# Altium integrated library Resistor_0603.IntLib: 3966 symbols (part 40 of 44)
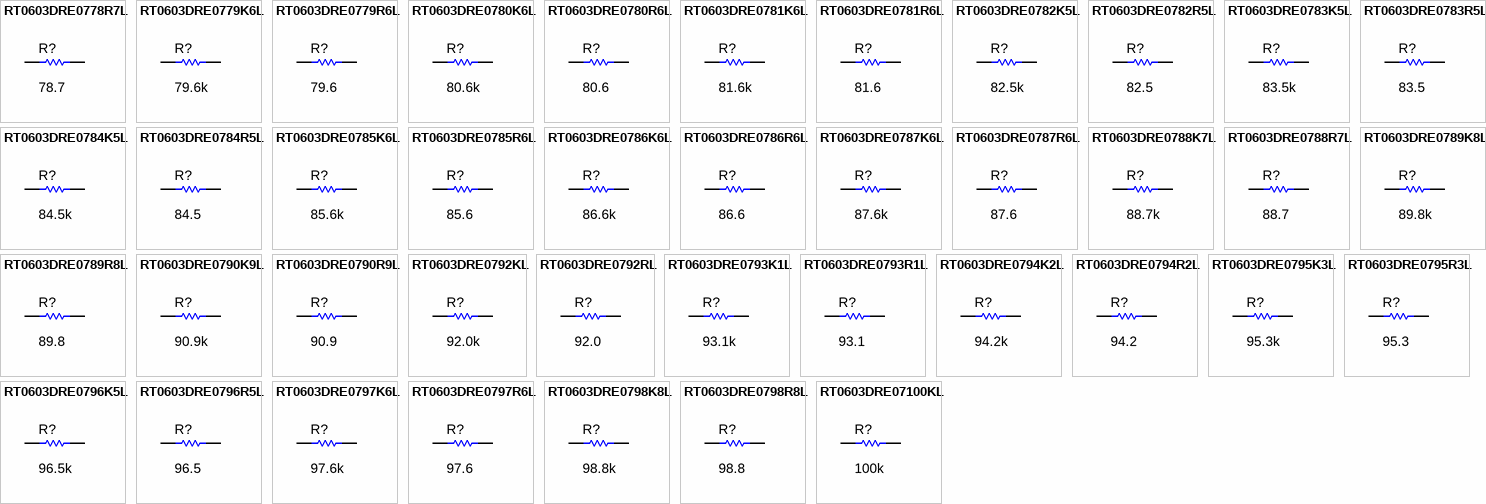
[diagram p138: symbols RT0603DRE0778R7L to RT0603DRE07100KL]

## RT0603DRE0779K6L
designator R?  ValueDisplayed: 79.6k  (hidden comment: RT0603DRE0779K6L)
RES, 79.6 k, 0.5%, 0.1 W, 0603; Manufacturer: Yageo America; CompType: Resistor; Value: 79.6k; Res_ohm: 79600; Value_Code: 79k6; Tolerance_%: 0.5; Power_W: 0.1; Value2: 0.1W; VDC_V: 75; TempCo: 50 ppm/C; SizeArea_mm2: 1.28; SizeX_mm: 1.6; SizeY_mm: 0.8; SizeZ_mm: 1; EIA_Code: E192; U/M: EA; AEC Category: Q200
signal-integrity model Resistor
simulation model Resistor
footprint 0603
footprint 0603M
footprint 0603L
footprint 0603_HV
footprint 0603S
pins: 1, 2

## RT0603DRE0779R6L
designator R?  ValueDisplayed: 79.6  (hidden comment: RT0603DRE0779R6L)
RES, 79.6, 0.5%, 0.1 W, 0603; Manufacturer: Yageo America; CompType: Resistor; Value: 79.6; Value_Code: 79R6; Tolerance_%: 0.5; Power_W: 0.1; Value2: 0.1W; VDC_V: 75; TempCo: 50 ppm/C; SizeArea_mm2: 1.28; SizeX_mm: 1.6; SizeY_mm: 0.8; SizeZ_mm: 1; EIA_Code: E192; U/M: EA; AEC Category: Q200
signal-integrity model Resistor
simulation model Resistor
footprint 0603
footprint 0603M
footprint 0603L
footprint 0603_HV
footprint 0603S
pins: 1, 2

## RT0603DRE0780K6L
designator R?  ValueDisplayed: 80.6k  (hidden comment: RT0603DRE0780K6L)
RES, 80.6 k, 0.5%, 0.1 W, 0603; Manufacturer: Yageo America; CompType: Resistor; Value: 80.6k; Res_ohm: 80600; Value_Code: 80k6; Tolerance_%: 0.5; Power_W: 0.1; Value2: 0.1W; VDC_V: 75; TempCo: 50 ppm/C; SizeArea_mm2: 1.28; SizeX_mm: 1.6; SizeY_mm: 0.8; SizeZ_mm: 1; EIA_Code: E192; U/M: EA; AEC Category: Q200
signal-integrity model Resistor
simulation model Resistor
footprint 0603
footprint 0603M
footprint 0603L
footprint 0603_HV
footprint 0603S
pins: 1, 2

## RT0603DRE0780R6L
designator R?  ValueDisplayed: 80.6  (hidden comment: RT0603DRE0780R6L)
RES, 80.6, 0.5%, 0.1 W, 0603; Manufacturer: Yageo America; CompType: Resistor; Value: 80.6; Value_Code: 80R6; Tolerance_%: 0.5; Power_W: 0.1; Value2: 0.1W; VDC_V: 75; TempCo: 50 ppm/C; SizeArea_mm2: 1.28; SizeX_mm: 1.6; SizeY_mm: 0.8; SizeZ_mm: 1; EIA_Code: E192; U/M: EA; AEC Category: Q200
signal-integrity model Resistor
simulation model Resistor
footprint 0603
footprint 0603M
footprint 0603L
footprint 0603_HV
footprint 0603S
pins: 1, 2

## RT0603DRE0781K6L
designator R?  ValueDisplayed: 81.6k  (hidden comment: RT0603DRE0781K6L)
RES, 81.6 k, 0.5%, 0.1 W, 0603; Manufacturer: Yageo America; CompType: Resistor; Value: 81.6k; Res_ohm: 81600; Value_Code: 81k6; Tolerance_%: 0.5; Power_W: 0.1; Value2: 0.1W; VDC_V: 75; TempCo: 50 ppm/C; SizeArea_mm2: 1.28; SizeX_mm: 1.6; SizeY_mm: 0.8; SizeZ_mm: 1; EIA_Code: E192; U/M: EA; AEC Category: Q200
signal-integrity model Resistor
simulation model Resistor
footprint 0603
footprint 0603M
footprint 0603L
footprint 0603_HV
footprint 0603S
pins: 1, 2

## RT0603DRE0781R6L
designator R?  ValueDisplayed: 81.6  (hidden comment: RT0603DRE0781R6L)
RES, 81.6, 0.5%, 0.1 W, 0603; Manufacturer: Yageo America; CompType: Resistor; Value: 81.6; Value_Code: 81R6; Tolerance_%: 0.5; Power_W: 0.1; Value2: 0.1W; VDC_V: 75; TempCo: 50 ppm/C; SizeArea_mm2: 1.28; SizeX_mm: 1.6; SizeY_mm: 0.8; SizeZ_mm: 1; EIA_Code: E192; U/M: EA; AEC Category: Q200
signal-integrity model Resistor
simulation model Resistor
footprint 0603
footprint 0603M
footprint 0603L
footprint 0603_HV
footprint 0603S
pins: 1, 2

## RT0603DRE0782K5L
designator R?  ValueDisplayed: 82.5k  (hidden comment: RT0603DRE0782K5L)
RES, 82.5 k, 0.5%, 0.1 W, 0603; Manufacturer: Yageo America; CompType: Resistor; Value: 82.5k; Res_ohm: 82500; Value_Code: 82k5; Tolerance_%: 0.5; Power_W: 0.1; Value2: 0.1W; VDC_V: 75; TempCo: 50 ppm/C; SizeArea_mm2: 1.28; SizeX_mm: 1.6; SizeY_mm: 0.8; SizeZ_mm: 1; EIA_Code: E192; U/M: EA; AEC Category: Q200
signal-integrity model Resistor
simulation model Resistor
footprint 0603
footprint 0603M
footprint 0603L
footprint 0603_HV
footprint 0603S
pins: 1, 2

## RT0603DRE0782R5L
designator R?  ValueDisplayed: 82.5  (hidden comment: RT0603DRE0782R5L)
RES, 82.5, 0.5%, 0.1 W, 0603; Manufacturer: Yageo America; CompType: Resistor; Value: 82.5; Value_Code: 82R5; Tolerance_%: 0.5; Power_W: 0.1; Value2: 0.1W; VDC_V: 75; TempCo: 50 ppm/C; SizeArea_mm2: 1.28; SizeX_mm: 1.6; SizeY_mm: 0.8; SizeZ_mm: 1; EIA_Code: E192; U/M: EA; AEC Category: Q200
signal-integrity model Resistor
simulation model Resistor
footprint 0603
footprint 0603M
footprint 0603L
footprint 0603_HV
footprint 0603S
pins: 1, 2

## RT0603DRE0783K5L
designator R?  ValueDisplayed: 83.5k  (hidden comment: RT0603DRE0783K5L)
RES, 83.5 k, 0.5%, 0.1 W, 0603; Manufacturer: Yageo America; CompType: Resistor; Value: 83.5k; Res_ohm: 83500; Value_Code: 83k5; Tolerance_%: 0.5; Power_W: 0.1; Value2: 0.1W; VDC_V: 75; TempCo: 50 ppm/C; SizeArea_mm2: 1.28; SizeX_mm: 1.6; SizeY_mm: 0.8; SizeZ_mm: 1; EIA_Code: E192; U/M: EA; AEC Category: Q200
signal-integrity model Resistor
simulation model Resistor
footprint 0603
footprint 0603M
footprint 0603L
footprint 0603_HV
footprint 0603S
pins: 1, 2

## RT0603DRE0783R5L
designator R?  ValueDisplayed: 83.5  (hidden comment: RT0603DRE0783R5L)
RES, 83.5, 0.5%, 0.1 W, 0603; Manufacturer: Yageo America; CompType: Resistor; Value: 83.5; Value_Code: 83R5; Tolerance_%: 0.5; Power_W: 0.1; Value2: 0.1W; VDC_V: 75; TempCo: 50 ppm/C; SizeArea_mm2: 1.28; SizeX_mm: 1.6; SizeY_mm: 0.8; SizeZ_mm: 1; EIA_Code: E192; U/M: EA; AEC Category: Q200
signal-integrity model Resistor
simulation model Resistor
footprint 0603
footprint 0603M
footprint 0603L
footprint 0603_HV
footprint 0603S
pins: 1, 2

## RT0603DRE0784K5L
designator R?  ValueDisplayed: 84.5k  (hidden comment: RT0603DRE0784K5L)
RES, 84.5 k, 0.5%, 0.1 W, 0603; Manufacturer: Yageo America; CompType: Resistor; Value: 84.5k; Res_ohm: 84500; Value_Code: 84k5; Tolerance_%: 0.5; Power_W: 0.1; Value2: 0.1W; VDC_V: 75; TempCo: 50 ppm/C; SizeArea_mm2: 1.28; SizeX_mm: 1.6; SizeY_mm: 0.8; SizeZ_mm: 1; EIA_Code: E192; U/M: EA; AEC Category: Q200
signal-integrity model Resistor
simulation model Resistor
footprint 0603
footprint 0603M
footprint 0603L
footprint 0603_HV
footprint 0603S
pins: 1, 2

## RT0603DRE0784R5L
designator R?  ValueDisplayed: 84.5  (hidden comment: RT0603DRE0784R5L)
RES, 84.5, 0.5%, 0.1 W, 0603; Manufacturer: Yageo America; CompType: Resistor; Value: 84.5; Value_Code: 84R5; Tolerance_%: 0.5; Power_W: 0.1; Value2: 0.1W; VDC_V: 75; TempCo: 50 ppm/C; SizeArea_mm2: 1.28; SizeX_mm: 1.6; SizeY_mm: 0.8; SizeZ_mm: 1; EIA_Code: E192; U/M: EA; AEC Category: Q200
signal-integrity model Resistor
simulation model Resistor
footprint 0603
footprint 0603M
footprint 0603L
footprint 0603_HV
footprint 0603S
pins: 1, 2

## RT0603DRE0785K6L
designator R?  ValueDisplayed: 85.6k  (hidden comment: RT0603DRE0785K6L)
RES, 85.6 k, 0.5%, 0.1 W, 0603; Manufacturer: Yageo America; CompType: Resistor; Value: 85.6k; Res_ohm: 85600; Value_Code: 85k6; Tolerance_%: 0.5; Power_W: 0.1; Value2: 0.1W; VDC_V: 75; TempCo: 50 ppm/C; SizeArea_mm2: 1.28; SizeX_mm: 1.6; SizeY_mm: 0.8; SizeZ_mm: 1; EIA_Code: E192; U/M: EA; AEC Category: Q200
signal-integrity model Resistor
simulation model Resistor
footprint 0603
footprint 0603M
footprint 0603L
footprint 0603_HV
footprint 0603S
pins: 1, 2

## RT0603DRE0785R6L
designator R?  ValueDisplayed: 85.6  (hidden comment: RT0603DRE0785R6L)
RES, 85.6, 0.5%, 0.1 W, 0603; Manufacturer: Yageo America; CompType: Resistor; Value: 85.6; Value_Code: 85R6; Tolerance_%: 0.5; Power_W: 0.1; Value2: 0.1W; VDC_V: 75; TempCo: 50 ppm/C; SizeArea_mm2: 1.28; SizeX_mm: 1.6; SizeY_mm: 0.8; SizeZ_mm: 1; EIA_Code: E192; U/M: EA; AEC Category: Q200
signal-integrity model Resistor
simulation model Resistor
footprint 0603
footprint 0603M
footprint 0603L
footprint 0603_HV
footprint 0603S
pins: 1, 2

## RT0603DRE0786K6L
designator R?  ValueDisplayed: 86.6k  (hidden comment: RT0603DRE0786K6L)
RES, 86.6 k, 0.5%, 0.1 W, 0603; Manufacturer: Yageo America; CompType: Resistor; Value: 86.6k; Res_ohm: 86600; Value_Code: 86k6; Tolerance_%: 0.5; Power_W: 0.1; Value2: 0.1W; VDC_V: 75; TempCo: 50 ppm/C; SizeArea_mm2: 1.28; SizeX_mm: 1.6; SizeY_mm: 0.8; SizeZ_mm: 1; EIA_Code: E192; U/M: EA; AEC Category: Q200
signal-integrity model Resistor
simulation model Resistor
footprint 0603
footprint 0603M
footprint 0603L
footprint 0603_HV
footprint 0603S
pins: 1, 2

## RT0603DRE0786R6L
designator R?  ValueDisplayed: 86.6  (hidden comment: RT0603DRE0786R6L)
RES, 86.6, 0.5%, 0.1 W, 0603; Manufacturer: Yageo America; CompType: Resistor; Value: 86.6; Value_Code: 86R6; Tolerance_%: 0.5; Power_W: 0.1; Value2: 0.1W; VDC_V: 75; TempCo: 50 ppm/C; SizeArea_mm2: 1.28; SizeX_mm: 1.6; SizeY_mm: 0.8; SizeZ_mm: 1; EIA_Code: E192; U/M: EA; AEC Category: Q200
signal-integrity model Resistor
simulation model Resistor
footprint 0603
footprint 0603M
footprint 0603L
footprint 0603_HV
footprint 0603S
pins: 1, 2

## RT0603DRE0787K6L
designator R?  ValueDisplayed: 87.6k  (hidden comment: RT0603DRE0787K6L)
RES, 87.6 k, 0.5%, 0.1 W, 0603; Manufacturer: Yageo America; CompType: Resistor; Value: 87.6k; Res_ohm: 87600; Value_Code: 87k6; Tolerance_%: 0.5; Power_W: 0.1; Value2: 0.1W; VDC_V: 75; TempCo: 50 ppm/C; SizeArea_mm2: 1.28; SizeX_mm: 1.6; SizeY_mm: 0.8; SizeZ_mm: 1; EIA_Code: E192; U/M: EA; AEC Category: Q200
signal-integrity model Resistor
simulation model Resistor
footprint 0603
footprint 0603M
footprint 0603L
footprint 0603_HV
footprint 0603S
pins: 1, 2

## RT0603DRE0787R6L
designator R?  ValueDisplayed: 87.6  (hidden comment: RT0603DRE0787R6L)
RES, 87.6, 0.5%, 0.1 W, 0603; Manufacturer: Yageo America; CompType: Resistor; Value: 87.6; Value_Code: 87R6; Tolerance_%: 0.5; Power_W: 0.1; Value2: 0.1W; VDC_V: 75; TempCo: 50 ppm/C; SizeArea_mm2: 1.28; SizeX_mm: 1.6; SizeY_mm: 0.8; SizeZ_mm: 1; EIA_Code: E192; U/M: EA; AEC Category: Q200
signal-integrity model Resistor
simulation model Resistor
footprint 0603
footprint 0603M
footprint 0603L
footprint 0603_HV
footprint 0603S
pins: 1, 2

## RT0603DRE0788K7L
designator R?  ValueDisplayed: 88.7k  (hidden comment: RT0603DRE0788K7L)
RES, 88.7 k, 0.5%, 0.1 W, 0603; Manufacturer: Yageo America; CompType: Resistor; Value: 88.7k; Res_ohm: 88700; Value_Code: 88k7; Tolerance_%: 0.5; Power_W: 0.1; Value2: 0.1W; VDC_V: 75; TempCo: 50 ppm/C; SizeArea_mm2: 1.28; SizeX_mm: 1.6; SizeY_mm: 0.8; SizeZ_mm: 1; EIA_Code: E192; U/M: EA; AEC Category: Q200
signal-integrity model Resistor
simulation model Resistor
footprint 0603
footprint 0603M
footprint 0603L
footprint 0603_HV
footprint 0603S
pins: 1, 2

## RT0603DRE0788R7L
designator R?  ValueDisplayed: 88.7  (hidden comment: RT0603DRE0788R7L)
RES, 88.7, 0.5%, 0.1 W, 0603; Manufacturer: Yageo America; CompType: Resistor; Value: 88.7; Value_Code: 88R7; Tolerance_%: 0.5; Power_W: 0.1; Value2: 0.1W; VDC_V: 75; TempCo: 50 ppm/C; SizeArea_mm2: 1.28; SizeX_mm: 1.6; SizeY_mm: 0.8; SizeZ_mm: 1; EIA_Code: E192; U/M: EA; AEC Category: Q200
signal-integrity model Resistor
simulation model Resistor
footprint 0603
footprint 0603M
footprint 0603L
footprint 0603_HV
footprint 0603S
pins: 1, 2

## RT0603DRE0789K8L
designator R?  ValueDisplayed: 89.8k  (hidden comment: RT0603DRE0789K8L)
RES, 89.8 k, 0.5%, 0.1 W, 0603; Manufacturer: Yageo America; CompType: Resistor; Value: 89.8k; Res_ohm: 89800; Value_Code: 89k8; Tolerance_%: 0.5; Power_W: 0.1; Value2: 0.1W; VDC_V: 75; TempCo: 50 ppm/C; SizeArea_mm2: 1.28; SizeX_mm: 1.6; SizeY_mm: 0.8; SizeZ_mm: 1; EIA_Code: E192; U/M: EA; AEC Category: Q200
signal-integrity model Resistor
simulation model Resistor
footprint 0603
footprint 0603M
footprint 0603L
footprint 0603_HV
footprint 0603S
pins: 1, 2

## RT0603DRE0789R8L
designator R?  ValueDisplayed: 89.8  (hidden comment: RT0603DRE0789R8L)
RES, 89.8, 0.5%, 0.1 W, 0603; Manufacturer: Yageo America; CompType: Resistor; Value: 89.8; Value_Code: 89R8; Tolerance_%: 0.5; Power_W: 0.1; Value2: 0.1W; VDC_V: 75; TempCo: 50 ppm/C; SizeArea_mm2: 1.28; SizeX_mm: 1.6; SizeY_mm: 0.8; SizeZ_mm: 1; EIA_Code: E192; U/M: EA; AEC Category: Q200
signal-integrity model Resistor
simulation model Resistor
footprint 0603
footprint 0603M
footprint 0603L
footprint 0603_HV
footprint 0603S
pins: 1, 2

## RT0603DRE0790K9L
designator R?  ValueDisplayed: 90.9k  (hidden comment: RT0603DRE0790K9L)
RES, 90.9 k, 0.5%, 0.1 W, 0603; Manufacturer: Yageo America; CompType: Resistor; Value: 90.9k; Res_ohm: 90900; Value_Code: 90k9; Tolerance_%: 0.5; Power_W: 0.1; Value2: 0.1W; VDC_V: 75; TempCo: 50 ppm/C; SizeArea_mm2: 1.28; SizeX_mm: 1.6; SizeY_mm: 0.8; SizeZ_mm: 1; EIA_Code: E192; U/M: EA; AEC Category: Q200
signal-integrity model Resistor
simulation model Resistor
footprint 0603
footprint 0603M
footprint 0603L
footprint 0603_HV
footprint 0603S
pins: 1, 2

## RT0603DRE0790R9L
designator R?  ValueDisplayed: 90.9  (hidden comment: RT0603DRE0790R9L)
RES, 90.9, 0.5%, 0.1 W, 0603; Manufacturer: Yageo America; CompType: Resistor; Value: 90.9; Value_Code: 90R9; Tolerance_%: 0.5; Power_W: 0.1; Value2: 0.1W; VDC_V: 75; TempCo: 50 ppm/C; SizeArea_mm2: 1.28; SizeX_mm: 1.6; SizeY_mm: 0.8; SizeZ_mm: 1; EIA_Code: E192; U/M: EA; AEC Category: Q200
signal-integrity model Resistor
simulation model Resistor
footprint 0603
footprint 0603M
footprint 0603L
footprint 0603_HV
footprint 0603S
pins: 1, 2

## RT0603DRE0792KL
designator R?  ValueDisplayed: 92.0k  (hidden comment: RT0603DRE0792KL)
RES, 92.0 k, 0.5%, 0.1 W, 0603; Manufacturer: Yageo America; CompType: Resistor; Value: 92.0k; Res_ohm: 92000; Value_Code: 92k0; Tolerance_%: 0.5; Power_W: 0.1; Value2: 0.1W; VDC_V: 75; TempCo: 50 ppm/C; SizeArea_mm2: 1.28; SizeX_mm: 1.6; SizeY_mm: 0.8; SizeZ_mm: 1; EIA_Code: E192; U/M: EA; AEC Category: Q200
signal-integrity model Resistor
simulation model Resistor
footprint 0603
footprint 0603M
footprint 0603L
footprint 0603_HV
footprint 0603S
pins: 1, 2

## RT0603DRE0792RL
designator R?  ValueDisplayed: 92.0  (hidden comment: RT0603DRE0792RL)
RES, 92.0, 0.5%, 0.1 W, 0603; Manufacturer: Yageo America; CompType: Resistor; Value: 92.0; Res_ohm: 92; Value_Code: 92R0; Tolerance_%: 0.5; Power_W: 0.1; Value2: 0.1W; VDC_V: 75; TempCo: 50 ppm/C; SizeArea_mm2: 1.28; SizeX_mm: 1.6; SizeY_mm: 0.8; SizeZ_mm: 1; EIA_Code: E192; U/M: EA; AEC Category: Q200
signal-integrity model Resistor
simulation model Resistor
footprint 0603
footprint 0603M
footprint 0603L
footprint 0603_HV
footprint 0603S
pins: 1, 2

## RT0603DRE0793K1L
designator R?  ValueDisplayed: 93.1k  (hidden comment: RT0603DRE0793K1L)
RES, 93.1 k, 0.5%, 0.1 W, 0603; Manufacturer: Yageo America; CompType: Resistor; Value: 93.1k; Res_ohm: 93100; Value_Code: 93k1; Tolerance_%: 0.5; Power_W: 0.1; Value2: 0.1W; VDC_V: 75; TempCo: 50 ppm/C; SizeArea_mm2: 1.28; SizeX_mm: 1.6; SizeY_mm: 0.8; SizeZ_mm: 1; EIA_Code: E192; U/M: EA; AEC Category: Q200
signal-integrity model Resistor
simulation model Resistor
footprint 0603
footprint 0603M
footprint 0603L
footprint 0603_HV
footprint 0603S
pins: 1, 2

## RT0603DRE0793R1L
designator R?  ValueDisplayed: 93.1  (hidden comment: RT0603DRE0793R1L)
RES, 93.1, 0.5%, 0.1 W, 0603; Manufacturer: Yageo America; CompType: Resistor; Value: 93.1; Value_Code: 93R1; Tolerance_%: 0.5; Power_W: 0.1; Value2: 0.1W; VDC_V: 75; TempCo: 50 ppm/C; SizeArea_mm2: 1.28; SizeX_mm: 1.6; SizeY_mm: 0.8; SizeZ_mm: 1; EIA_Code: E192; U/M: EA; AEC Category: Q200
signal-integrity model Resistor
simulation model Resistor
footprint 0603
footprint 0603M
footprint 0603L
footprint 0603_HV
footprint 0603S
pins: 1, 2

## RT0603DRE0794K2L
designator R?  ValueDisplayed: 94.2k  (hidden comment: RT0603DRE0794K2L)
RES, 94.2 k, 0.5%, 0.1 W, 0603; Manufacturer: Yageo America; CompType: Resistor; Value: 94.2k; Res_ohm: 94200; Value_Code: 94k2; Tolerance_%: 0.5; Power_W: 0.1; Value2: 0.1W; VDC_V: 75; TempCo: 50 ppm/C; SizeArea_mm2: 1.28; SizeX_mm: 1.6; SizeY_mm: 0.8; SizeZ_mm: 1; EIA_Code: E192; U/M: EA; AEC Category: Q200
signal-integrity model Resistor
simulation model Resistor
footprint 0603
footprint 0603M
footprint 0603L
footprint 0603_HV
footprint 0603S
pins: 1, 2

## RT0603DRE0794R2L
designator R?  ValueDisplayed: 94.2  (hidden comment: RT0603DRE0794R2L)
RES, 94.2, 0.5%, 0.1 W, 0603; Manufacturer: Yageo America; CompType: Resistor; Value: 94.2; Value_Code: 94R2; Tolerance_%: 0.5; Power_W: 0.1; Value2: 0.1W; VDC_V: 75; TempCo: 50 ppm/C; SizeArea_mm2: 1.28; SizeX_mm: 1.6; SizeY_mm: 0.8; SizeZ_mm: 1; EIA_Code: E192; U/M: EA; AEC Category: Q200
signal-integrity model Resistor
simulation model Resistor
footprint 0603
footprint 0603M
footprint 0603L
footprint 0603_HV
footprint 0603S
pins: 1, 2

## RT0603DRE0795K3L
designator R?  ValueDisplayed: 95.3k  (hidden comment: RT0603DRE0795K3L)
RES, 95.3 k, 0.5%, 0.1 W, 0603; Manufacturer: Yageo America; CompType: Resistor; Value: 95.3k; Res_ohm: 95300; Value_Code: 95k3; Tolerance_%: 0.5; Power_W: 0.1; Value2: 0.1W; VDC_V: 75; TempCo: 50 ppm/C; SizeArea_mm2: 1.28; SizeX_mm: 1.6; SizeY_mm: 0.8; SizeZ_mm: 1; EIA_Code: E192; U/M: EA; AEC Category: Q200
signal-integrity model Resistor
simulation model Resistor
footprint 0603
footprint 0603M
footprint 0603L
footprint 0603_HV
footprint 0603S
pins: 1, 2

## RT0603DRE0795R3L
designator R?  ValueDisplayed: 95.3  (hidden comment: RT0603DRE0795R3L)
RES, 95.3, 0.5%, 0.1 W, 0603; Manufacturer: Yageo America; CompType: Resistor; Value: 95.3; Value_Code: 95R3; Tolerance_%: 0.5; Power_W: 0.1; Value2: 0.1W; VDC_V: 75; TempCo: 50 ppm/C; SizeArea_mm2: 1.28; SizeX_mm: 1.6; SizeY_mm: 0.8; SizeZ_mm: 1; EIA_Code: E192; U/M: EA; AEC Category: Q200
signal-integrity model Resistor
simulation model Resistor
footprint 0603
footprint 0603M
footprint 0603L
footprint 0603_HV
footprint 0603S
pins: 1, 2

## RT0603DRE0796K5L
designator R?  ValueDisplayed: 96.5k  (hidden comment: RT0603DRE0796K5L)
RES, 96.5 k, 0.5%, 0.1 W, 0603; Manufacturer: Yageo America; CompType: Resistor; Value: 96.5k; Res_ohm: 96500; Value_Code: 96k5; Tolerance_%: 0.5; Power_W: 0.1; Value2: 0.1W; VDC_V: 75; TempCo: 50 ppm/C; SizeArea_mm2: 1.28; SizeX_mm: 1.6; SizeY_mm: 0.8; SizeZ_mm: 1; EIA_Code: E192; U/M: EA; AEC Category: Q200
signal-integrity model Resistor
simulation model Resistor
footprint 0603
footprint 0603M
footprint 0603L
footprint 0603_HV
footprint 0603S
pins: 1, 2

## RT0603DRE0796R5L
designator R?  ValueDisplayed: 96.5  (hidden comment: RT0603DRE0796R5L)
RES, 96.5, 0.5%, 0.1 W, 0603; Manufacturer: Yageo America; CompType: Resistor; Value: 96.5; Value_Code: 96R5; Tolerance_%: 0.5; Power_W: 0.1; Value2: 0.1W; VDC_V: 75; TempCo: 50 ppm/C; SizeArea_mm2: 1.28; SizeX_mm: 1.6; SizeY_mm: 0.8; SizeZ_mm: 1; EIA_Code: E192; U/M: EA; AEC Category: Q200
signal-integrity model Resistor
simulation model Resistor
footprint 0603
footprint 0603M
footprint 0603L
footprint 0603_HV
footprint 0603S
pins: 1, 2

## RT0603DRE0797K6L
designator R?  ValueDisplayed: 97.6k  (hidden comment: RT0603DRE0797K6L)
RES, 97.6 k, 0.5%, 0.1 W, 0603; Manufacturer: Yageo America; CompType: Resistor; Value: 97.6k; Res_ohm: 97600; Value_Code: 97k6; Tolerance_%: 0.5; Power_W: 0.1; Value2: 0.1W; VDC_V: 75; TempCo: 50 ppm/C; SizeArea_mm2: 1.28; SizeX_mm: 1.6; SizeY_mm: 0.8; SizeZ_mm: 1; EIA_Code: E192; U/M: EA; AEC Category: Q200
signal-integrity model Resistor
simulation model Resistor
footprint 0603
footprint 0603M
footprint 0603L
footprint 0603_HV
footprint 0603S
pins: 1, 2

## RT0603DRE0797R6L
designator R?  ValueDisplayed: 97.6  (hidden comment: RT0603DRE0797R6L)
RES, 97.6, 0.5%, 0.1 W, 0603; Manufacturer: Yageo America; CompType: Resistor; Value: 97.6; Value_Code: 97R6; Tolerance_%: 0.5; Power_W: 0.1; Value2: 0.1W; VDC_V: 75; TempCo: 50 ppm/C; SizeArea_mm2: 1.28; SizeX_mm: 1.6; SizeY_mm: 0.8; SizeZ_mm: 1; EIA_Code: E192; U/M: EA; AEC Category: Q200
signal-integrity model Resistor
simulation model Resistor
footprint 0603
footprint 0603M
footprint 0603L
footprint 0603_HV
footprint 0603S
pins: 1, 2

## RT0603DRE0798K8L
designator R?  ValueDisplayed: 98.8k  (hidden comment: RT0603DRE0798K8L)
RES, 98.8 k, 0.5%, 0.1 W, 0603; Manufacturer: Yageo America; CompType: Resistor; Value: 98.8k; Res_ohm: 98800; Value_Code: 98k8; Tolerance_%: 0.5; Power_W: 0.1; Value2: 0.1W; VDC_V: 75; TempCo: 50 ppm/C; SizeArea_mm2: 1.28; SizeX_mm: 1.6; SizeY_mm: 0.8; SizeZ_mm: 1; EIA_Code: E192; U/M: EA; AEC Category: Q200
signal-integrity model Resistor
simulation model Resistor
footprint 0603
footprint 0603M
footprint 0603L
footprint 0603_HV
footprint 0603S
pins: 1, 2

## RT0603DRE0798R8L
designator R?  ValueDisplayed: 98.8  (hidden comment: RT0603DRE0798R8L)
RES, 98.8, 0.5%, 0.1 W, 0603; Manufacturer: Yageo America; CompType: Resistor; Value: 98.8; Value_Code: 98R8; Tolerance_%: 0.5; Power_W: 0.1; Value2: 0.1W; VDC_V: 75; TempCo: 50 ppm/C; SizeArea_mm2: 1.28; SizeX_mm: 1.6; SizeY_mm: 0.8; SizeZ_mm: 1; EIA_Code: E192; U/M: EA; AEC Category: Q200
signal-integrity model Resistor
simulation model Resistor
footprint 0603
footprint 0603M
footprint 0603L
footprint 0603_HV
footprint 0603S
pins: 1, 2

## RT0603DRE07100KL
designator R?  ValueDisplayed: 100k  (hidden comment: RT0603DRE07100KL)
RES, 100 k, 0.5%, 0.1 W, 0603; Manufacturer: Yageo America; CompType: Resistor; Value: 100k; Res_ohm: 100000; Tolerance_%: 0.5; Power_W: 0.1; Value2: 0.1W; VDC_V: 75; TempCo: 50 ppm/C; SizeArea_mm2: 1.28; SizeX_mm: 1.6; SizeY_mm: 0.8; SizeZ_mm: 1; EIA_Code: E192; U/M: EA; AEC Category: Q200
signal-integrity model Resistor
simulation model Resistor
footprint 0603
footprint 0603M
footprint 0603L
footprint 0603_HV
footprint 0603S
pins: 1, 2

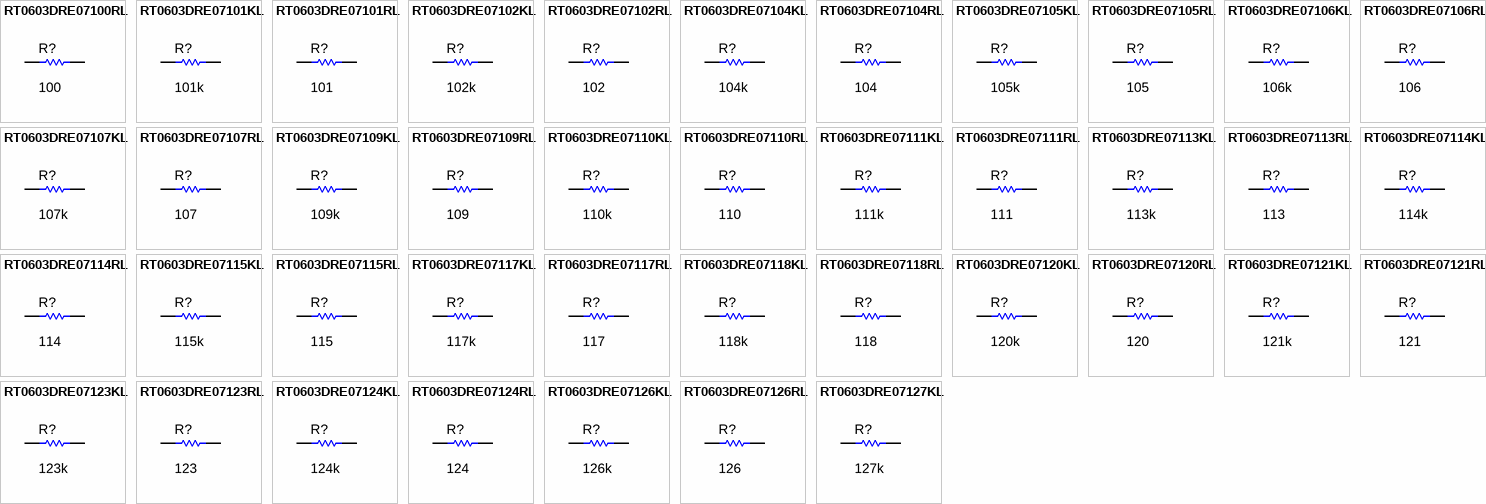
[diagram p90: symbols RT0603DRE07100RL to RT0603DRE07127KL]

## RT0603DRE07100RL
designator R?  ValueDisplayed: 100  (hidden comment: RT0603DRE07100RL)
RES, 100, 0.5%, 0.1 W, 0603; Manufacturer: Yageo America; CompType: Resistor; Value: 100; Value_Code: 100R; Tolerance_%: 0.5; Power_W: 0.1; Value2: 0.1W; VDC_V: 75; TempCo: 50 ppm/C; SizeArea_mm2: 1.28; SizeX_mm: 1.6; SizeY_mm: 0.8; SizeZ_mm: 1; EIA_Code: E192; U/M: EA; AEC Category: Q200
signal-integrity model Resistor
simulation model Resistor
footprint 0603
footprint 0603M
footprint 0603L
footprint 0603_HV
footprint 0603S
pins: 1, 2

## RT0603DRE07101KL
designator R?  ValueDisplayed: 101k  (hidden comment: RT0603DRE07101KL)
RES, 101 k, 0.5%, 0.1 W, 0603; Manufacturer: Yageo America; CompType: Resistor; Value: 101k; Res_ohm: 101000; Tolerance_%: 0.5; Power_W: 0.1; Value2: 0.1W; VDC_V: 75; TempCo: 50 ppm/C; SizeArea_mm2: 1.28; SizeX_mm: 1.6; SizeY_mm: 0.8; SizeZ_mm: 1; EIA_Code: E192; U/M: EA; AEC Category: Q200
signal-integrity model Resistor
simulation model Resistor
footprint 0603
footprint 0603M
footprint 0603L
footprint 0603_HV
footprint 0603S
pins: 1, 2

## RT0603DRE07101RL
designator R?  ValueDisplayed: 101  (hidden comment: RT0603DRE07101RL)
RES, 101, 0.5%, 0.1 W, 0603; Manufacturer: Yageo America; CompType: Resistor; Value: 101; Value_Code: 101R; Tolerance_%: 0.5; Power_W: 0.1; Value2: 0.1W; VDC_V: 75; TempCo: 50 ppm/C; SizeArea_mm2: 1.28; SizeX_mm: 1.6; SizeY_mm: 0.8; SizeZ_mm: 1; EIA_Code: E192; U/M: EA; AEC Category: Q200
signal-integrity model Resistor
simulation model Resistor
footprint 0603
footprint 0603M
footprint 0603L
footprint 0603_HV
footprint 0603S
pins: 1, 2

## RT0603DRE07102KL
designator R?  ValueDisplayed: 102k  (hidden comment: RT0603DRE07102KL)
RES, 102 k, 0.5%, 0.1 W, 0603; Manufacturer: Yageo America; CompType: Resistor; Value: 102k; Res_ohm: 102000; Tolerance_%: 0.5; Power_W: 0.1; Value2: 0.1W; VDC_V: 75; TempCo: 50 ppm/C; SizeArea_mm2: 1.28; SizeX_mm: 1.6; SizeY_mm: 0.8; SizeZ_mm: 1; EIA_Code: E192; U/M: EA; AEC Category: Q200
signal-integrity model Resistor
simulation model Resistor
footprint 0603
footprint 0603M
footprint 0603L
footprint 0603_HV
footprint 0603S
pins: 1, 2

## RT0603DRE07102RL
designator R?  ValueDisplayed: 102  (hidden comment: RT0603DRE07102RL)
RES, 102, 0.5%, 0.1 W, 0603; Manufacturer: Yageo America; CompType: Resistor; Value: 102; Value_Code: 102R; Tolerance_%: 0.5; Power_W: 0.1; Value2: 0.1W; VDC_V: 75; TempCo: 50 ppm/C; SizeArea_mm2: 1.28; SizeX_mm: 1.6; SizeY_mm: 0.8; SizeZ_mm: 1; EIA_Code: E192; U/M: EA; AEC Category: Q200
signal-integrity model Resistor
simulation model Resistor
footprint 0603
footprint 0603M
footprint 0603L
footprint 0603_HV
footprint 0603S
pins: 1, 2

## RT0603DRE07104KL
designator R?  ValueDisplayed: 104k  (hidden comment: RT0603DRE07104KL)
RES, 104 k, 0.5%, 0.1 W, 0603; Manufacturer: Yageo America; CompType: Resistor; Value: 104k; Res_ohm: 104000; Tolerance_%: 0.5; Power_W: 0.1; Value2: 0.1W; VDC_V: 75; TempCo: 50 ppm/C; SizeArea_mm2: 1.28; SizeX_mm: 1.6; SizeY_mm: 0.8; SizeZ_mm: 1; EIA_Code: E192; U/M: EA; AEC Category: Q200
signal-integrity model Resistor
simulation model Resistor
footprint 0603
footprint 0603M
footprint 0603L
footprint 0603_HV
footprint 0603S
pins: 1, 2

## RT0603DRE07104RL
designator R?  ValueDisplayed: 104  (hidden comment: RT0603DRE07104RL)
RES, 104, 0.5%, 0.1 W, 0603; Manufacturer: Yageo America; CompType: Resistor; Value: 104; Value_Code: 104R; Tolerance_%: 0.5; Power_W: 0.1; Value2: 0.1W; VDC_V: 75; TempCo: 50 ppm/C; SizeArea_mm2: 1.28; SizeX_mm: 1.6; SizeY_mm: 0.8; SizeZ_mm: 1; EIA_Code: E192; U/M: EA; AEC Category: Q200
signal-integrity model Resistor
simulation model Resistor
footprint 0603
footprint 0603M
footprint 0603L
footprint 0603_HV
footprint 0603S
pins: 1, 2

## RT0603DRE07105KL
designator R?  ValueDisplayed: 105k  (hidden comment: RT0603DRE07105KL)
RES, 105 k, 0.5%, 0.1 W, 0603; Manufacturer: Yageo America; CompType: Resistor; Value: 105k; Res_ohm: 105000; Tolerance_%: 0.5; Power_W: 0.1; Value2: 0.1W; VDC_V: 75; TempCo: 50 ppm/C; SizeArea_mm2: 1.28; SizeX_mm: 1.6; SizeY_mm: 0.8; SizeZ_mm: 1; EIA_Code: E192; U/M: EA; AEC Category: Q200
signal-integrity model Resistor
simulation model Resistor
footprint 0603
footprint 0603M
footprint 0603L
footprint 0603_HV
footprint 0603S
pins: 1, 2

## RT0603DRE07105RL
designator R?  ValueDisplayed: 105  (hidden comment: RT0603DRE07105RL)
RES, 105, 0.5%, 0.1 W, 0603; Manufacturer: Yageo America; CompType: Resistor; Value: 105; Value_Code: 105R; Tolerance_%: 0.5; Power_W: 0.1; Value2: 0.1W; VDC_V: 75; TempCo: 50 ppm/C; SizeArea_mm2: 1.28; SizeX_mm: 1.6; SizeY_mm: 0.8; SizeZ_mm: 1; EIA_Code: E192; U/M: EA; AEC Category: Q200
signal-integrity model Resistor
simulation model Resistor
footprint 0603
footprint 0603M
footprint 0603L
footprint 0603_HV
footprint 0603S
pins: 1, 2

## RT0603DRE07106KL
designator R?  ValueDisplayed: 106k  (hidden comment: RT0603DRE07106KL)
RES, 106 k, 0.5%, 0.1 W, 0603; Manufacturer: Yageo America; CompType: Resistor; Value: 106k; Res_ohm: 106000; Tolerance_%: 0.5; Power_W: 0.1; Value2: 0.1W; VDC_V: 75; TempCo: 50 ppm/C; SizeArea_mm2: 1.28; SizeX_mm: 1.6; SizeY_mm: 0.8; SizeZ_mm: 1; EIA_Code: E192; U/M: EA; AEC Category: Q200
signal-integrity model Resistor
simulation model Resistor
footprint 0603
footprint 0603M
footprint 0603L
footprint 0603_HV
footprint 0603S
pins: 1, 2

## RT0603DRE07106RL
designator R?  ValueDisplayed: 106  (hidden comment: RT0603DRE07106RL)
RES, 106, 0.5%, 0.1 W, 0603; Manufacturer: Yageo America; CompType: Resistor; Value: 106; Value_Code: 106R; Tolerance_%: 0.5; Power_W: 0.1; Value2: 0.1W; VDC_V: 75; TempCo: 50 ppm/C; SizeArea_mm2: 1.28; SizeX_mm: 1.6; SizeY_mm: 0.8; SizeZ_mm: 1; EIA_Code: E192; U/M: EA; AEC Category: Q200
signal-integrity model Resistor
simulation model Resistor
footprint 0603
footprint 0603M
footprint 0603L
footprint 0603_HV
footprint 0603S
pins: 1, 2

## RT0603DRE07107KL
designator R?  ValueDisplayed: 107k  (hidden comment: RT0603DRE07107KL)
RES, 107 k, 0.5%, 0.1 W, 0603; Manufacturer: Yageo America; CompType: Resistor; Value: 107k; Res_ohm: 107000; Tolerance_%: 0.5; Power_W: 0.1; Value2: 0.1W; VDC_V: 75; TempCo: 50 ppm/C; SizeArea_mm2: 1.28; SizeX_mm: 1.6; SizeY_mm: 0.8; SizeZ_mm: 1; EIA_Code: E192; U/M: EA; AEC Category: Q200
signal-integrity model Resistor
simulation model Resistor
footprint 0603
footprint 0603M
footprint 0603L
footprint 0603_HV
footprint 0603S
pins: 1, 2

## RT0603DRE07107RL
designator R?  ValueDisplayed: 107  (hidden comment: RT0603DRE07107RL)
RES, 107, 0.5%, 0.1 W, 0603; Manufacturer: Yageo America; CompType: Resistor; Value: 107; Value_Code: 107R; Tolerance_%: 0.5; Power_W: 0.1; Value2: 0.1W; VDC_V: 75; TempCo: 50 ppm/C; SizeArea_mm2: 1.28; SizeX_mm: 1.6; SizeY_mm: 0.8; SizeZ_mm: 1; EIA_Code: E192; U/M: EA; AEC Category: Q200
signal-integrity model Resistor
simulation model Resistor
footprint 0603
footprint 0603M
footprint 0603L
footprint 0603_HV
footprint 0603S
pins: 1, 2

## RT0603DRE07109KL
designator R?  ValueDisplayed: 109k  (hidden comment: RT0603DRE07109KL)
RES, 109 k, 0.5%, 0.1 W, 0603; Manufacturer: Yageo America; CompType: Resistor; Value: 109k; Res_ohm: 109000; Tolerance_%: 0.5; Power_W: 0.1; Value2: 0.1W; VDC_V: 75; TempCo: 50 ppm/C; SizeArea_mm2: 1.28; SizeX_mm: 1.6; SizeY_mm: 0.8; SizeZ_mm: 1; EIA_Code: E192; U/M: EA; AEC Category: Q200
signal-integrity model Resistor
simulation model Resistor
footprint 0603
footprint 0603M
footprint 0603L
footprint 0603_HV
footprint 0603S
pins: 1, 2

## RT0603DRE07109RL
designator R?  ValueDisplayed: 109  (hidden comment: RT0603DRE07109RL)
RES, 109, 0.5%, 0.1 W, 0603; Manufacturer: Yageo America; CompType: Resistor; Value: 109; Value_Code: 109R; Tolerance_%: 0.5; Power_W: 0.1; Value2: 0.1W; VDC_V: 75; TempCo: 50 ppm/C; SizeArea_mm2: 1.28; SizeX_mm: 1.6; SizeY_mm: 0.8; SizeZ_mm: 1; EIA_Code: E192; U/M: EA; AEC Category: Q200
signal-integrity model Resistor
simulation model Resistor
footprint 0603
footprint 0603M
footprint 0603L
footprint 0603_HV
footprint 0603S
pins: 1, 2

## RT0603DRE07110KL
designator R?  ValueDisplayed: 110k  (hidden comment: RT0603DRE07110KL)
RES, 110 k, 0.5%, 0.1 W, 0603; Manufacturer: Yageo America; CompType: Resistor; Value: 110k; Res_ohm: 110000; Tolerance_%: 0.5; Power_W: 0.1; Value2: 0.1W; VDC_V: 75; TempCo: 50 ppm/C; SizeArea_mm2: 1.28; SizeX_mm: 1.6; SizeY_mm: 0.8; SizeZ_mm: 1; EIA_Code: E192; U/M: EA; AEC Category: Q200
signal-integrity model Resistor
simulation model Resistor
footprint 0603
footprint 0603M
footprint 0603L
footprint 0603_HV
footprint 0603S
pins: 1, 2

## RT0603DRE07110RL
designator R?  ValueDisplayed: 110  (hidden comment: RT0603DRE07110RL)
RES, 110, 0.5%, 0.1 W, 0603; Manufacturer: Yageo America; CompType: Resistor; Value: 110; Value_Code: 110R; Tolerance_%: 0.5; Power_W: 0.1; Value2: 0.1W; VDC_V: 75; TempCo: 50 ppm/C; SizeArea_mm2: 1.28; SizeX_mm: 1.6; SizeY_mm: 0.8; SizeZ_mm: 1; EIA_Code: E192; U/M: EA; AEC Category: Q200
signal-integrity model Resistor
simulation model Resistor
footprint 0603
footprint 0603M
footprint 0603L
footprint 0603_HV
footprint 0603S
pins: 1, 2

## RT0603DRE07111KL
designator R?  ValueDisplayed: 111k  (hidden comment: RT0603DRE07111KL)
RES, 111 k, 0.5%, 0.1 W, 0603; Manufacturer: Yageo America; CompType: Resistor; Value: 111k; Res_ohm: 111000; Tolerance_%: 0.5; Power_W: 0.1; Value2: 0.1W; VDC_V: 75; TempCo: 50 ppm/C; SizeArea_mm2: 1.28; SizeX_mm: 1.6; SizeY_mm: 0.8; SizeZ_mm: 1; EIA_Code: E192; U/M: EA; AEC Category: Q200
signal-integrity model Resistor
simulation model Resistor
footprint 0603
footprint 0603M
footprint 0603L
footprint 0603_HV
footprint 0603S
pins: 1, 2

## RT0603DRE07111RL
designator R?  ValueDisplayed: 111  (hidden comment: RT0603DRE07111RL)
RES, 111, 0.5%, 0.1 W, 0603; Manufacturer: Yageo America; CompType: Resistor; Value: 111; Value_Code: 111R; Tolerance_%: 0.5; Power_W: 0.1; Value2: 0.1W; VDC_V: 75; TempCo: 50 ppm/C; SizeArea_mm2: 1.28; SizeX_mm: 1.6; SizeY_mm: 0.8; SizeZ_mm: 1; EIA_Code: E192; U/M: EA; AEC Category: Q200
signal-integrity model Resistor
simulation model Resistor
footprint 0603
footprint 0603M
footprint 0603L
footprint 0603_HV
footprint 0603S
pins: 1, 2

## RT0603DRE07113KL
designator R?  ValueDisplayed: 113k  (hidden comment: RT0603DRE07113KL)
RES, 113 k, 0.5%, 0.1 W, 0603; Manufacturer: Yageo America; CompType: Resistor; Value: 113k; Res_ohm: 113000; Tolerance_%: 0.5; Power_W: 0.1; Value2: 0.1W; VDC_V: 75; TempCo: 50 ppm/C; SizeArea_mm2: 1.28; SizeX_mm: 1.6; SizeY_mm: 0.8; SizeZ_mm: 1; EIA_Code: E192; U/M: EA; AEC Category: Q200
signal-integrity model Resistor
simulation model Resistor
footprint 0603
footprint 0603M
footprint 0603L
footprint 0603_HV
footprint 0603S
pins: 1, 2

## RT0603DRE07113RL
designator R?  ValueDisplayed: 113  (hidden comment: RT0603DRE07113RL)
RES, 113, 0.5%, 0.1 W, 0603; Manufacturer: Yageo America; CompType: Resistor; Value: 113; Value_Code: 113R; Tolerance_%: 0.5; Power_W: 0.1; Value2: 0.1W; VDC_V: 75; TempCo: 50 ppm/C; SizeArea_mm2: 1.28; SizeX_mm: 1.6; SizeY_mm: 0.8; SizeZ_mm: 1; EIA_Code: E192; U/M: EA; AEC Category: Q200
signal-integrity model Resistor
simulation model Resistor
footprint 0603
footprint 0603M
footprint 0603L
footprint 0603_HV
footprint 0603S
pins: 1, 2

## RT0603DRE07114KL
designator R?  ValueDisplayed: 114k  (hidden comment: RT0603DRE07114KL)
RES, 114 k, 0.5%, 0.1 W, 0603; Manufacturer: Yageo America; CompType: Resistor; Value: 114k; Res_ohm: 114000; Tolerance_%: 0.5; Power_W: 0.1; Value2: 0.1W; VDC_V: 75; TempCo: 50 ppm/C; SizeArea_mm2: 1.28; SizeX_mm: 1.6; SizeY_mm: 0.8; SizeZ_mm: 1; EIA_Code: E192; U/M: EA; AEC Category: Q200
signal-integrity model Resistor
simulation model Resistor
footprint 0603
footprint 0603M
footprint 0603L
footprint 0603_HV
footprint 0603S
pins: 1, 2

## RT0603DRE07114RL
designator R?  ValueDisplayed: 114  (hidden comment: RT0603DRE07114RL)
RES, 114, 0.5%, 0.1 W, 0603; Manufacturer: Yageo America; CompType: Resistor; Value: 114; Value_Code: 114R; Tolerance_%: 0.5; Power_W: 0.1; Value2: 0.1W; VDC_V: 75; TempCo: 50 ppm/C; SizeArea_mm2: 1.28; SizeX_mm: 1.6; SizeY_mm: 0.8; SizeZ_mm: 1; EIA_Code: E192; U/M: EA; AEC Category: Q200
signal-integrity model Resistor
simulation model Resistor
footprint 0603
footprint 0603M
footprint 0603L
footprint 0603_HV
footprint 0603S
pins: 1, 2

## RT0603DRE07115KL
designator R?  ValueDisplayed: 115k  (hidden comment: RT0603DRE07115KL)
RES, 115 k, 0.5%, 0.1 W, 0603; Manufacturer: Yageo America; CompType: Resistor; Value: 115k; Res_ohm: 115000; Tolerance_%: 0.5; Power_W: 0.1; Value2: 0.1W; VDC_V: 75; TempCo: 50 ppm/C; SizeArea_mm2: 1.28; SizeX_mm: 1.6; SizeY_mm: 0.8; SizeZ_mm: 1; EIA_Code: E192; U/M: EA; AEC Category: Q200
signal-integrity model Resistor
simulation model Resistor
footprint 0603
footprint 0603M
footprint 0603L
footprint 0603_HV
footprint 0603S
pins: 1, 2

## RT0603DRE07115RL
designator R?  ValueDisplayed: 115  (hidden comment: RT0603DRE07115RL)
RES, 115, 0.5%, 0.1 W, 0603; Manufacturer: Yageo America; CompType: Resistor; Value: 115; Value_Code: 115R; Tolerance_%: 0.5; Power_W: 0.1; Value2: 0.1W; VDC_V: 75; TempCo: 50 ppm/C; SizeArea_mm2: 1.28; SizeX_mm: 1.6; SizeY_mm: 0.8; SizeZ_mm: 1; EIA_Code: E192; U/M: EA; AEC Category: Q200
signal-integrity model Resistor
simulation model Resistor
footprint 0603
footprint 0603M
footprint 0603L
footprint 0603_HV
footprint 0603S
pins: 1, 2

## RT0603DRE07117KL
designator R?  ValueDisplayed: 117k  (hidden comment: RT0603DRE07117KL)
RES, 117 k, 0.5%, 0.1 W, 0603; Manufacturer: Yageo America; CompType: Resistor; Value: 117k; Res_ohm: 117000; Tolerance_%: 0.5; Power_W: 0.1; Value2: 0.1W; VDC_V: 75; TempCo: 50 ppm/C; SizeArea_mm2: 1.28; SizeX_mm: 1.6; SizeY_mm: 0.8; SizeZ_mm: 1; EIA_Code: E192; U/M: EA; AEC Category: Q200
signal-integrity model Resistor
simulation model Resistor
footprint 0603
footprint 0603M
footprint 0603L
footprint 0603_HV
footprint 0603S
pins: 1, 2

## RT0603DRE07117RL
designator R?  ValueDisplayed: 117  (hidden comment: RT0603DRE07117RL)
RES, 117, 0.5%, 0.1 W, 0603; Manufacturer: Yageo America; CompType: Resistor; Value: 117; Value_Code: 117R; Tolerance_%: 0.5; Power_W: 0.1; Value2: 0.1W; VDC_V: 75; TempCo: 50 ppm/C; SizeArea_mm2: 1.28; SizeX_mm: 1.6; SizeY_mm: 0.8; SizeZ_mm: 1; EIA_Code: E192; U/M: EA; AEC Category: Q200
signal-integrity model Resistor
simulation model Resistor
footprint 0603
footprint 0603M
footprint 0603L
footprint 0603_HV
footprint 0603S
pins: 1, 2

## RT0603DRE07118KL
designator R?  ValueDisplayed: 118k  (hidden comment: RT0603DRE07118KL)
RES, 118 k, 0.5%, 0.1 W, 0603; Manufacturer: Yageo America; CompType: Resistor; Value: 118k; Res_ohm: 118000; Tolerance_%: 0.5; Power_W: 0.1; Value2: 0.1W; VDC_V: 75; TempCo: 50 ppm/C; SizeArea_mm2: 1.28; SizeX_mm: 1.6; SizeY_mm: 0.8; SizeZ_mm: 1; EIA_Code: E192; U/M: EA; AEC Category: Q200
signal-integrity model Resistor
simulation model Resistor
footprint 0603
footprint 0603M
footprint 0603L
footprint 0603_HV
footprint 0603S
pins: 1, 2

## RT0603DRE07118RL
designator R?  ValueDisplayed: 118  (hidden comment: RT0603DRE07118RL)
RES, 118, 0.5%, 0.1 W, 0603; Manufacturer: Yageo America; CompType: Resistor; Value: 118; Value_Code: 118R; Tolerance_%: 0.5; Power_W: 0.1; Value2: 0.1W; VDC_V: 75; TempCo: 50 ppm/C; SizeArea_mm2: 1.28; SizeX_mm: 1.6; SizeY_mm: 0.8; SizeZ_mm: 1; EIA_Code: E192; U/M: EA; AEC Category: Q200
signal-integrity model Resistor
simulation model Resistor
footprint 0603
footprint 0603M
footprint 0603L
footprint 0603_HV
footprint 0603S
pins: 1, 2

## RT0603DRE07120KL
designator R?  ValueDisplayed: 120k  (hidden comment: RT0603DRE07120KL)
RES, 120 k, 0.5%, 0.1 W, 0603; Manufacturer: Yageo America; CompType: Resistor; Value: 120k; Res_ohm: 120000; Tolerance_%: 0.5; Power_W: 0.1; Value2: 0.1W; VDC_V: 75; TempCo: 50 ppm/C; SizeArea_mm2: 1.28; SizeX_mm: 1.6; SizeY_mm: 0.8; SizeZ_mm: 1; EIA_Code: E192; U/M: EA; AEC Category: Q200; Green_Lifecycle: Active; Green_REACh: Passed
signal-integrity model Resistor
simulation model Resistor
footprint 0603
footprint 0603M
footprint 0603L
footprint 0603_HV
footprint 0603S
pins: 1, 2

## RT0603DRE07120RL
designator R?  ValueDisplayed: 120  (hidden comment: RT0603DRE07120RL)
RES, 120, 0.5%, 0.1 W, 0603; Manufacturer: Yageo America; CompType: Resistor; Value: 120; Value_Code: 120R; Tolerance_%: 0.5; Power_W: 0.1; Value2: 0.1W; VDC_V: 75; TempCo: 50 ppm/C; SizeArea_mm2: 1.28; SizeX_mm: 1.6; SizeY_mm: 0.8; SizeZ_mm: 1; EIA_Code: E192; U/M: EA; AEC Category: Q200
signal-integrity model Resistor
simulation model Resistor
footprint 0603
footprint 0603M
footprint 0603L
footprint 0603_HV
footprint 0603S
pins: 1, 2

## RT0603DRE07121KL
designator R?  ValueDisplayed: 121k  (hidden comment: RT0603DRE07121KL)
RES, 121 k, 0.5%, 0.1 W, 0603; Manufacturer: Yageo America; CompType: Resistor; Value: 121k; Res_ohm: 121000; Tolerance_%: 0.5; Power_W: 0.1; Value2: 0.1W; VDC_V: 75; TempCo: 50 ppm/C; SizeArea_mm2: 1.28; SizeX_mm: 1.6; SizeY_mm: 0.8; SizeZ_mm: 1; EIA_Code: E192; U/M: EA; AEC Category: Q200
signal-integrity model Resistor
simulation model Resistor
footprint 0603
footprint 0603M
footprint 0603L
footprint 0603_HV
footprint 0603S
pins: 1, 2

## RT0603DRE07121RL
designator R?  ValueDisplayed: 121  (hidden comment: RT0603DRE07121RL)
RES, 121, 0.5%, 0.1 W, 0603; Manufacturer: Yageo America; CompType: Resistor; Value: 121; Value_Code: 121R; Tolerance_%: 0.5; Power_W: 0.1; Value2: 0.1W; VDC_V: 75; TempCo: 50 ppm/C; SizeArea_mm2: 1.28; SizeX_mm: 1.6; SizeY_mm: 0.8; SizeZ_mm: 1; EIA_Code: E192; U/M: EA; AEC Category: Q200
signal-integrity model Resistor
simulation model Resistor
footprint 0603
footprint 0603M
footprint 0603L
footprint 0603_HV
footprint 0603S
pins: 1, 2

## RT0603DRE07123KL
designator R?  ValueDisplayed: 123k  (hidden comment: RT0603DRE07123KL)
RES, 123 k, 0.5%, 0.1 W, 0603; Manufacturer: Yageo America; CompType: Resistor; Value: 123k; Res_ohm: 123000; Tolerance_%: 0.5; Power_W: 0.1; Value2: 0.1W; VDC_V: 75; TempCo: 50 ppm/C; SizeArea_mm2: 1.28; SizeX_mm: 1.6; SizeY_mm: 0.8; SizeZ_mm: 1; EIA_Code: E192; U/M: EA; AEC Category: Q200
signal-integrity model Resistor
simulation model Resistor
footprint 0603
footprint 0603M
footprint 0603L
footprint 0603_HV
footprint 0603S
pins: 1, 2

## RT0603DRE07123RL
designator R?  ValueDisplayed: 123  (hidden comment: RT0603DRE07123RL)
RES, 123, 0.5%, 0.1 W, 0603; Manufacturer: Yageo America; CompType: Resistor; Value: 123; Value_Code: 123R; Tolerance_%: 0.5; Power_W: 0.1; Value2: 0.1W; VDC_V: 75; TempCo: 50 ppm/C; SizeArea_mm2: 1.28; SizeX_mm: 1.6; SizeY_mm: 0.8; SizeZ_mm: 1; EIA_Code: E192; U/M: EA; AEC Category: Q200
signal-integrity model Resistor
simulation model Resistor
footprint 0603
footprint 0603M
footprint 0603L
footprint 0603_HV
footprint 0603S
pins: 1, 2

## RT0603DRE07124KL
designator R?  ValueDisplayed: 124k  (hidden comment: RT0603DRE07124KL)
RES, 124 k, 0.5%, 0.1 W, 0603; Manufacturer: Yageo America; CompType: Resistor; Value: 124k; Res_ohm: 124000; Tolerance_%: 0.5; Power_W: 0.1; Value2: 0.1W; VDC_V: 75; TempCo: 50 ppm/C; SizeArea_mm2: 1.28; SizeX_mm: 1.6; SizeY_mm: 0.8; SizeZ_mm: 1; EIA_Code: E192; U/M: EA; AEC Category: Q200
signal-integrity model Resistor
simulation model Resistor
footprint 0603
footprint 0603M
footprint 0603L
footprint 0603_HV
footprint 0603S
pins: 1, 2

## RT0603DRE07124RL
designator R?  ValueDisplayed: 124  (hidden comment: RT0603DRE07124RL)
RES, 124, 0.5%, 0.1 W, 0603; Manufacturer: Yageo America; CompType: Resistor; Value: 124; Value_Code: 124R; Tolerance_%: 0.5; Power_W: 0.1; Value2: 0.1W; VDC_V: 75; TempCo: 50 ppm/C; SizeArea_mm2: 1.28; SizeX_mm: 1.6; SizeY_mm: 0.8; SizeZ_mm: 1; EIA_Code: E192; U/M: EA; AEC Category: Q200
signal-integrity model Resistor
simulation model Resistor
footprint 0603
footprint 0603M
footprint 0603L
footprint 0603_HV
footprint 0603S
pins: 1, 2

## RT0603DRE07126KL
designator R?  ValueDisplayed: 126k  (hidden comment: RT0603DRE07126KL)
RES, 126 k, 0.5%, 0.1 W, 0603; Manufacturer: Yageo America; CompType: Resistor; Value: 126k; Res_ohm: 126000; Tolerance_%: 0.5; Power_W: 0.1; Value2: 0.1W; VDC_V: 75; TempCo: 50 ppm/C; SizeArea_mm2: 1.28; SizeX_mm: 1.6; SizeY_mm: 0.8; SizeZ_mm: 1; EIA_Code: E192; U/M: EA; AEC Category: Q200
signal-integrity model Resistor
simulation model Resistor
footprint 0603
footprint 0603M
footprint 0603L
footprint 0603_HV
footprint 0603S
pins: 1, 2

## RT0603DRE07126RL
designator R?  ValueDisplayed: 126  (hidden comment: RT0603DRE07126RL)
RES, 126, 0.5%, 0.1 W, 0603; Manufacturer: Yageo America; CompType: Resistor; Value: 126; Value_Code: 126R; Tolerance_%: 0.5; Power_W: 0.1; Value2: 0.1W; VDC_V: 75; TempCo: 50 ppm/C; SizeArea_mm2: 1.28; SizeX_mm: 1.6; SizeY_mm: 0.8; SizeZ_mm: 1; EIA_Code: E192; U/M: EA; AEC Category: Q200
signal-integrity model Resistor
simulation model Resistor
footprint 0603
footprint 0603M
footprint 0603L
footprint 0603_HV
footprint 0603S
pins: 1, 2

## RT0603DRE07127KL
designator R?  ValueDisplayed: 127k  (hidden comment: RT0603DRE07127KL)
RES, 127 k, 0.5%, 0.1 W, 0603; Manufacturer: Yageo America; CompType: Resistor; Value: 127k; Res_ohm: 127000; Tolerance_%: 0.5; Power_W: 0.1; Value2: 0.1W; VDC_V: 75; TempCo: 50 ppm/C; SizeArea_mm2: 1.28; SizeX_mm: 1.6; SizeY_mm: 0.8; SizeZ_mm: 1; EIA_Code: E192; U/M: EA; AEC Category: Q200
signal-integrity model Resistor
simulation model Resistor
footprint 0603
footprint 0603M
footprint 0603L
footprint 0603_HV
footprint 0603S
pins: 1, 2

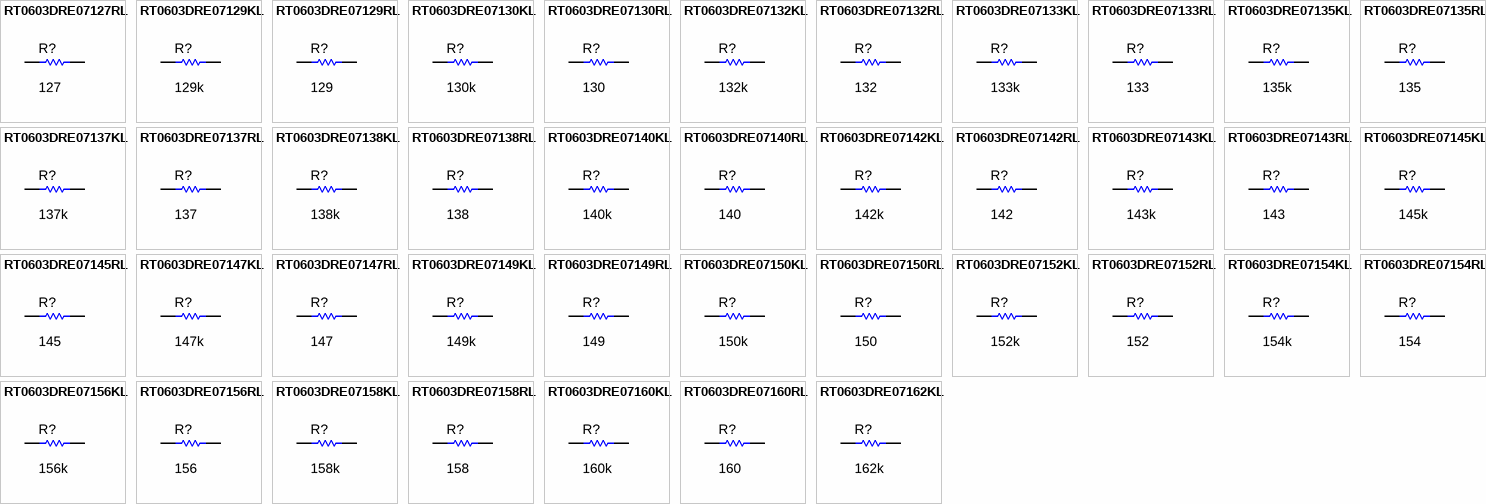
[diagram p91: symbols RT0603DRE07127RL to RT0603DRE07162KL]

## RT0603DRE07127RL
designator R?  ValueDisplayed: 127  (hidden comment: RT0603DRE07127RL)
RES, 127, 0.5%, 0.1 W, 0603; Manufacturer: Yageo America; CompType: Resistor; Value: 127; Value_Code: 127R; Tolerance_%: 0.5; Power_W: 0.1; Value2: 0.1W; VDC_V: 75; TempCo: 50 ppm/C; SizeArea_mm2: 1.28; SizeX_mm: 1.6; SizeY_mm: 0.8; SizeZ_mm: 1; EIA_Code: E192; U/M: EA; AEC Category: Q200
signal-integrity model Resistor
simulation model Resistor
footprint 0603
footprint 0603M
footprint 0603L
footprint 0603_HV
footprint 0603S
pins: 1, 2

## RT0603DRE07129KL
designator R?  ValueDisplayed: 129k  (hidden comment: RT0603DRE07129KL)
RES, 129 k, 0.5%, 0.1 W, 0603; Manufacturer: Yageo America; CompType: Resistor; Value: 129k; Res_ohm: 129000; Tolerance_%: 0.5; Power_W: 0.1; Value2: 0.1W; VDC_V: 75; TempCo: 50 ppm/C; SizeArea_mm2: 1.28; SizeX_mm: 1.6; SizeY_mm: 0.8; SizeZ_mm: 1; EIA_Code: E192; U/M: EA; AEC Category: Q200
signal-integrity model Resistor
simulation model Resistor
footprint 0603
footprint 0603M
footprint 0603L
footprint 0603_HV
footprint 0603S
pins: 1, 2

## RT0603DRE07129RL
designator R?  ValueDisplayed: 129  (hidden comment: RT0603DRE07129RL)
RES, 129, 0.5%, 0.1 W, 0603; Manufacturer: Yageo America; CompType: Resistor; Value: 129; Value_Code: 129R; Tolerance_%: 0.5; Power_W: 0.1; Value2: 0.1W; VDC_V: 75; TempCo: 50 ppm/C; SizeArea_mm2: 1.28; SizeX_mm: 1.6; SizeY_mm: 0.8; SizeZ_mm: 1; EIA_Code: E192; U/M: EA; AEC Category: Q200
signal-integrity model Resistor
simulation model Resistor
footprint 0603
footprint 0603M
footprint 0603L
footprint 0603_HV
footprint 0603S
pins: 1, 2

## RT0603DRE07130KL
designator R?  ValueDisplayed: 130k  (hidden comment: RT0603DRE07130KL)
RES, 130 k, 0.5%, 0.1 W, 0603; Manufacturer: Yageo America; CompType: Resistor; Value: 130k; Res_ohm: 130000; Tolerance_%: 0.5; Power_W: 0.1; Value2: 0.1W; VDC_V: 75; TempCo: 50 ppm/C; SizeArea_mm2: 1.28; SizeX_mm: 1.6; SizeY_mm: 0.8; SizeZ_mm: 1; EIA_Code: E192; U/M: EA; AEC Category: Q200
signal-integrity model Resistor
simulation model Resistor
footprint 0603
footprint 0603M
footprint 0603L
footprint 0603_HV
footprint 0603S
pins: 1, 2

## RT0603DRE07130RL
designator R?  ValueDisplayed: 130  (hidden comment: RT0603DRE07130RL)
RES, 130, 0.5%, 0.1 W, 0603; Manufacturer: Yageo America; CompType: Resistor; Value: 130; Value_Code: 130R; Tolerance_%: 0.5; Power_W: 0.1; Value2: 0.1W; VDC_V: 75; TempCo: 50 ppm/C; SizeArea_mm2: 1.28; SizeX_mm: 1.6; SizeY_mm: 0.8; SizeZ_mm: 1; EIA_Code: E192; U/M: EA; AEC Category: Q200
signal-integrity model Resistor
simulation model Resistor
footprint 0603
footprint 0603M
footprint 0603L
footprint 0603_HV
footprint 0603S
pins: 1, 2

## RT0603DRE07132KL
designator R?  ValueDisplayed: 132k  (hidden comment: RT0603DRE07132KL)
RES, 132 k, 0.5%, 0.1 W, 0603; Manufacturer: Yageo America; CompType: Resistor; Value: 132k; Res_ohm: 132000; Tolerance_%: 0.5; Power_W: 0.1; Value2: 0.1W; VDC_V: 75; TempCo: 50 ppm/C; SizeArea_mm2: 1.28; SizeX_mm: 1.6; SizeY_mm: 0.8; SizeZ_mm: 1; EIA_Code: E192; U/M: EA; AEC Category: Q200
signal-integrity model Resistor
simulation model Resistor
footprint 0603
footprint 0603M
footprint 0603L
footprint 0603_HV
footprint 0603S
pins: 1, 2

## RT0603DRE07132RL
designator R?  ValueDisplayed: 132  (hidden comment: RT0603DRE07132RL)
RES, 132, 0.5%, 0.1 W, 0603; Manufacturer: Yageo America; CompType: Resistor; Value: 132; Value_Code: 132R; Tolerance_%: 0.5; Power_W: 0.1; Value2: 0.1W; VDC_V: 75; TempCo: 50 ppm/C; SizeArea_mm2: 1.28; SizeX_mm: 1.6; SizeY_mm: 0.8; SizeZ_mm: 1; EIA_Code: E192; U/M: EA; AEC Category: Q200
signal-integrity model Resistor
simulation model Resistor
footprint 0603
footprint 0603M
footprint 0603L
footprint 0603_HV
footprint 0603S
pins: 1, 2

## RT0603DRE07133KL
designator R?  ValueDisplayed: 133k  (hidden comment: RT0603DRE07133KL)
RES, 133 k, 0.5%, 0.1 W, 0603; Manufacturer: Yageo America; CompType: Resistor; Value: 133k; Res_ohm: 133000; Tolerance_%: 0.5; Power_W: 0.1; Value2: 0.1W; VDC_V: 75; TempCo: 50 ppm/C; SizeArea_mm2: 1.28; SizeX_mm: 1.6; SizeY_mm: 0.8; SizeZ_mm: 1; EIA_Code: E192; U/M: EA; AEC Category: Q200
signal-integrity model Resistor
simulation model Resistor
footprint 0603
footprint 0603M
footprint 0603L
footprint 0603_HV
footprint 0603S
pins: 1, 2

## RT0603DRE07133RL
designator R?  ValueDisplayed: 133  (hidden comment: RT0603DRE07133RL)
RES, 133, 0.5%, 0.1 W, 0603; Manufacturer: Yageo America; CompType: Resistor; Value: 133; Value_Code: 133R; Tolerance_%: 0.5; Power_W: 0.1; Value2: 0.1W; VDC_V: 75; TempCo: 50 ppm/C; SizeArea_mm2: 1.28; SizeX_mm: 1.6; SizeY_mm: 0.8; SizeZ_mm: 1; EIA_Code: E192; U/M: EA; AEC Category: Q200
signal-integrity model Resistor
simulation model Resistor
footprint 0603
footprint 0603M
footprint 0603L
footprint 0603_HV
footprint 0603S
pins: 1, 2

## RT0603DRE07135KL
designator R?  ValueDisplayed: 135k  (hidden comment: RT0603DRE07135KL)
RES, 135 k, 0.5%, 0.1 W, 0603; Manufacturer: Yageo America; CompType: Resistor; Value: 135k; Res_ohm: 135000; Tolerance_%: 0.5; Power_W: 0.1; Value2: 0.1W; VDC_V: 75; TempCo: 50 ppm/C; SizeArea_mm2: 1.28; SizeX_mm: 1.6; SizeY_mm: 0.8; SizeZ_mm: 1; EIA_Code: E192; U/M: EA; AEC Category: Q200
signal-integrity model Resistor
simulation model Resistor
footprint 0603
footprint 0603M
footprint 0603L
footprint 0603_HV
footprint 0603S
pins: 1, 2

## RT0603DRE07135RL
designator R?  ValueDisplayed: 135  (hidden comment: RT0603DRE07135RL)
RES, 135, 0.5%, 0.1 W, 0603; Manufacturer: Yageo America; CompType: Resistor; Value: 135; Value_Code: 135R; Tolerance_%: 0.5; Power_W: 0.1; Value2: 0.1W; VDC_V: 75; TempCo: 50 ppm/C; SizeArea_mm2: 1.28; SizeX_mm: 1.6; SizeY_mm: 0.8; SizeZ_mm: 1; EIA_Code: E192; U/M: EA; AEC Category: Q200
signal-integrity model Resistor
simulation model Resistor
footprint 0603
footprint 0603M
footprint 0603L
footprint 0603_HV
footprint 0603S
pins: 1, 2

## RT0603DRE07137KL
designator R?  ValueDisplayed: 137k  (hidden comment: RT0603DRE07137KL)
RES, 137 k, 0.5%, 0.1 W, 0603; Manufacturer: Yageo America; CompType: Resistor; Value: 137k; Res_ohm: 137000; Tolerance_%: 0.5; Power_W: 0.1; Value2: 0.1W; VDC_V: 75; TempCo: 50 ppm/C; SizeArea_mm2: 1.28; SizeX_mm: 1.6; SizeY_mm: 0.8; SizeZ_mm: 1; EIA_Code: E192; U/M: EA; AEC Category: Q200
signal-integrity model Resistor
simulation model Resistor
footprint 0603
footprint 0603M
footprint 0603L
footprint 0603_HV
footprint 0603S
pins: 1, 2

## RT0603DRE07137RL
designator R?  ValueDisplayed: 137  (hidden comment: RT0603DRE07137RL)
RES, 137, 0.5%, 0.1 W, 0603; Manufacturer: Yageo America; CompType: Resistor; Value: 137; Value_Code: 137R; Tolerance_%: 0.5; Power_W: 0.1; Value2: 0.1W; VDC_V: 75; TempCo: 50 ppm/C; SizeArea_mm2: 1.28; SizeX_mm: 1.6; SizeY_mm: 0.8; SizeZ_mm: 1; EIA_Code: E192; U/M: EA; AEC Category: Q200
signal-integrity model Resistor
simulation model Resistor
footprint 0603
footprint 0603M
footprint 0603L
footprint 0603_HV
footprint 0603S
pins: 1, 2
